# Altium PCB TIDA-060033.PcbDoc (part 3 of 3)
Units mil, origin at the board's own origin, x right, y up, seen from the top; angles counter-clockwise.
Board outline 1900 x 3360 mil, 8 copper layers (Top Layer L1, GND Plane L2, GND Plane L3, GND/Signal L4, GND Plane L5, GND Plane L6, GND Plane L7, Bottom Layer L8), stack 61.4 mil thick; 78 components, 27 nets, 146 pads, 1944 vias.
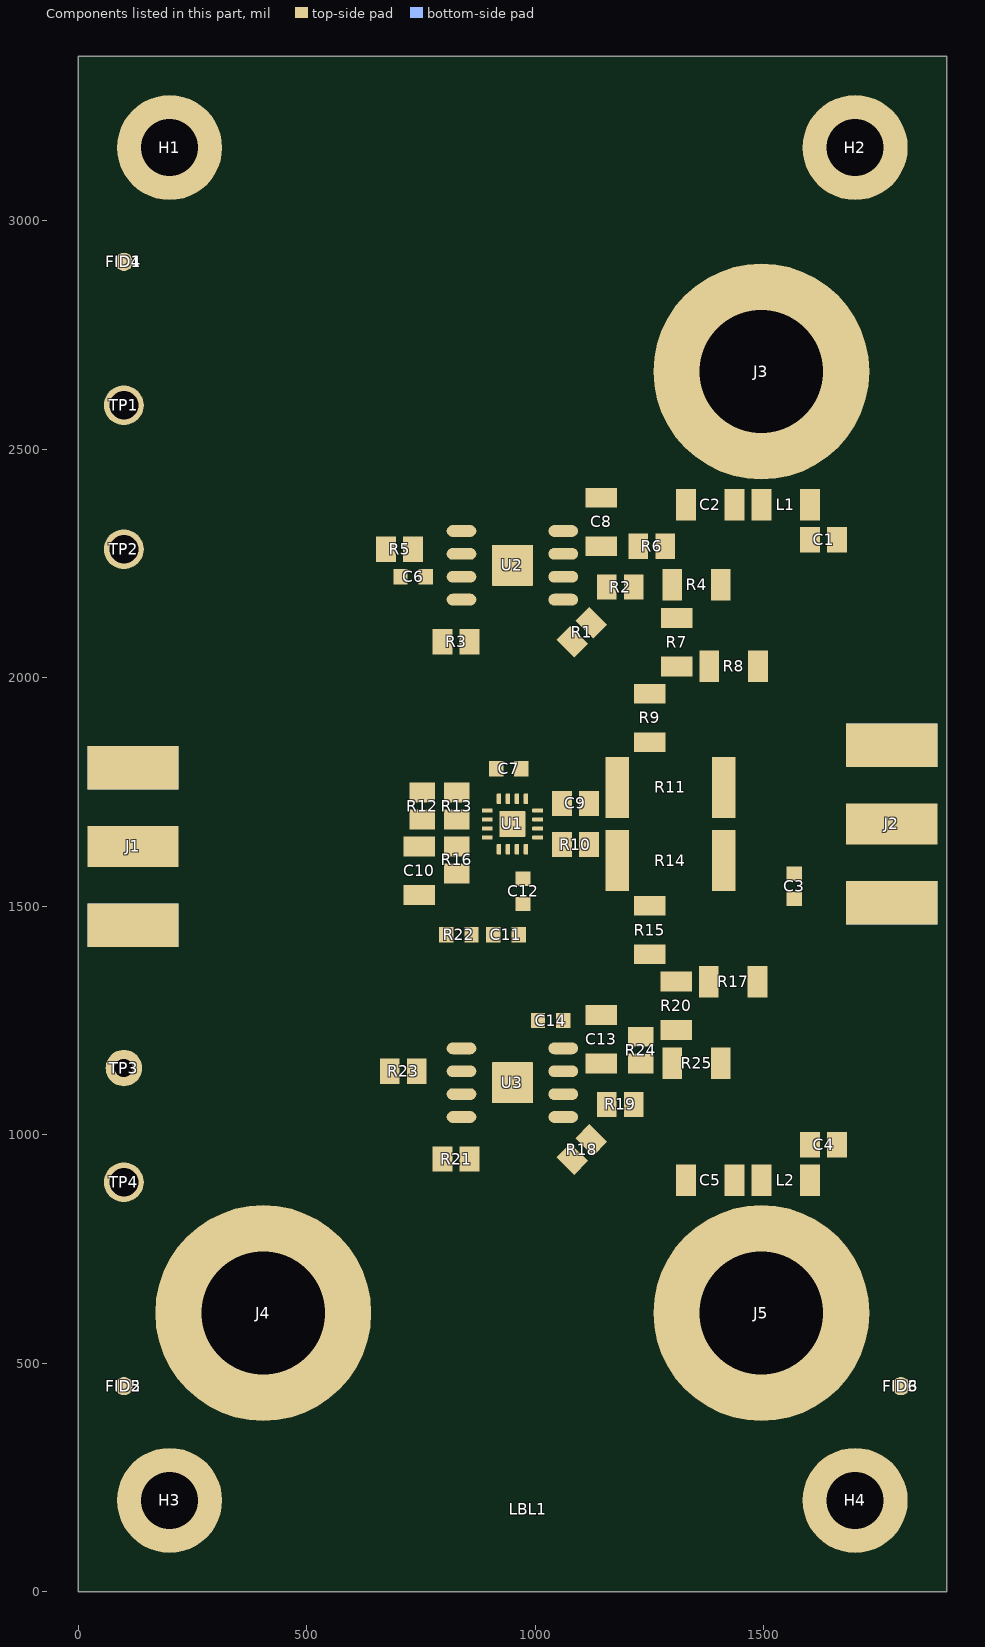
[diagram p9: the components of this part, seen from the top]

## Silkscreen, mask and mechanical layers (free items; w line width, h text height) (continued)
M9 Title Sheet:
  drawing of 57 lines, arcs and shapes, not listed
  text "1" at 739.84,8036.5 h70
  text "2" at 3235.5,8036.5 h70
  text "3" at 5724.84,8036.5 h70
  text "4" at 8231.51,8036.5 h70
  text "5" at 10730.5,8036.5 h70
  text "6" at 13235.5,8036.5 h70
  text "A" at -416.5,6893.5 h70
  text "A" at 14383.5,6893.5 h70
  text "B" at -416.5,4513.5 h70
  text "B" at 14383.5,4513.5 h70
  text "C" at -416.5,2138.5 h70
  text "C" at 14383.5,2138.5 h70
  text "PROJECT TITLE:" at 11343.5,277.5 h45
  text ".PRJ_Title" at 11393.5,144.17 h70
  text "DESIGNED FOR:" at 11343.5,-23.5 h45
  text ".PRJ_Customer" at 11393.5,-163.5 h70
  text "D" at -416.5,-231.5 h70
  text "D" at 14383.5,-231.5 h70
  text "FILE NAME:" at 11343.5,-323.5 h45
  text ".PCB_File_Name_No_Path" at 11393.5,-443.5 h70
  text "Texas Instruments (TI) and/or its licensors do not warrant the accuracy or completeness of this specification" at 6374,-605.34 h45
  text "ENGINEER:" at 11343.5,-613.5 h45
  text "LAYOUT BY:" at 12848.5,-613.5 h45
  text "or any information contained therein. TI and/or its licensors do not warrant that this design will meet" at 6329.01,-718 h45
  text ".PRJ_Engineer" at 11393.5,-768.49 h70
  text ".PCB_Layout" at 12899,-768.49 h70
  text "the specifications, will be suitable for your application or fit for any particular purpose, or will operate in" at 6329.01,-830.67 h45
  text ".Layer_Name" at 577,-858.49 h60
  text "ALTIUM DESIGNER VERSION:" at 12848.5,-923.5 h45
  text "an implementation. TI and/or its licensors do not warrant that the design is production worthy. You should" at 6329.01,-943.33 h45
  text "completely validate and test your design implementation to confirm the system functionality for your application." at 6374,-1056 h45
  text ".print_Scale" at 11393.5,-1056.83 h70
  text ".Application_BuildNumber" at 12899,-1056.83 h70
  text "1" at 739.84,-1263.5 h70
  text "2" at 3235.5,-1263.5 h70
  text "3" at 5724.84,-1263.5 h70
  text "4" at 8231.51,-1263.5 h70
  text "5" at 10730.5,-1263.5 h70
  text "6" at 13235.5,-1263.5 h70
M10 Fab Notes:
  drawing of 189 lines, arcs and shapes, not listed
  text "DESIGN INFORMATION" at 12382.02,6356.17 h60
  text "MIN. TRACK WIDTH:" at 11737.46,6224.05 h60
  text "8" at 12833.7,6224.05 h60
  text "MIL" at 12988.46,6224.05 h60
  text "MIN. CLEARANCE:" at 11737.46,6099.92 h60
  text "0.2" at 12773.7,6099.93 h60
  text "mm" at 12988.46,6099.92 h60
  text "MIN. VIA PAD SIZE:" at 11737.46,5975.8 h60
  text "24" at 12803.71,5975.8 h60
  text "MIL" at 12988.46,5975.8 h60
  text "0.05mm (2MIL)" at 12432.46,5845.9 h60
  text "MINIMUM ANNULAR RING" at 11408.23,5837.67 h60
  text "EXTERNAL" at 13140.46,5837.67 h60
  text "PER" at 11608.23,5727.55 h60
  text "IPC-D-275 CLASS 2 LEVEL C" at 11828.23,5727.54 h60
  text "MIL, HOLES" at 13316.46,5627.07 h60
  text "+/-" at 12924,5618.48 h60
  text "+/-" at 13778,5618.48 h60
  text "REGISTRATION TOLERANCES:" at 11408.23,5617.42 h60
  text "METAL" at 12608,5617.42 h60
  text "5" at 13184.2,5617.42 h60
  text "3" at 14017.2,5617.42 h60
  text "MIL" at 14133.46,5617.42 h60
  text "HOLE SIZE TOLERANCE (UNLESS OTHERWISE SPECIFIED):" at 11408.23,5519.1 h60
  text "+/-" at 13778,5516.23 h60
  text "3" at 14017.2,5515.17 h60
  text "MIL" at 14133.46,5515.17 h60
  text "MATERIAL:" at 11333.46,5377.52 h60
  text "FR-4 High Tg" at 12319.9,5249 h60
  text "X" at 12175.46,5241.01 h60
  text "FR-408" at 11754.46,5236.49 h60
  text "OTHER" at 13242.46,5236.49 h60
  text "62 MIL (1.6mm) +/-10%" at 12074.56,5093.46 h60
  text "X" at 11954.46,5091.01 h60
  text "THICKNESS:" at 11408.23,5085.24 h60
  text "OTHER" at 13359.46,5085.24 h60
  text "TOLERANCE:" at 11408.23,4946.92 h60
  text "X" at 12256.46,4946.92 h60
  text "ANSI IPC-6012 TYPE 3 CLASS 2" at 12434.48,4946.92 h60
  text "OTHER +/-" at 12434.46,4802.73 h60
  text "BOW & TWIST:" at 11408.23,4657.54 h60
  text "X" at 12256.46,4657.54 h60
  text "ANSI IPC-6012 TYPE 3 CLASS 2" at 12434.48,4657.54 h60
  text "OTHER +/-" at 12434.46,4510.85 h60
  text "DRILLING:" at 11333.46,4380.23 h60
  text "NC_DRILL FILES" at 13094.46,4275.04 h60
  text "REFERENCE:" at 11408.23,4271.1 h60
  text "X" at 12065.46,4271.01 h60
  text "AS SHOWN" at 12243.46,4271.1 h60
  text "X" at 12966.46,4271.1 h60
  text "OTHER" at 13392.46,4128.85 h60
  text "PTH COPPER THICKNESS:" at 11407.91,4125.32 h60
  text "X" at 12547.14,4125.32 h60
  text "20-30 um" at 12675.14,4125.32 h60
  text "BOARD FINISH:" at 11333.46,3977.73 h60
  text "SILKSCREEN:" at 11488.68,3867.6 h60
  text "X" at 12446.46,3867.6 h60
  text "TOP" at 12563.46,3867.6 h60
  text "X" at 12956.46,3867.6 h60
  text "BOTTOM" at 13074.46,3867.6 h60
  text "SILKSCREEN COLOR:" at 11488.68,3712.41 h60
  text "X" at 12445.46,3712.41 h60
  text "WHITE" at 12563.46,3712.41 h60
  text "OTHER" at 13074.46,3712.41 h60
  text "X" at 12576.46,3568.96 h60
  text "GREEN" at 12694.46,3568.96 h60
  text "OTHER" at 13312.46,3568.96 h60
  text "SOLDER RESIST COLOR:" at 11488.68,3562.1 h60
  text "X" at 12576.46,3414.71 h60
  text "MATTE" at 12694.46,3414.71 h60
  text "SEMI-GLOSS" at 13312,3414.07 h60
  text "IMMERSION GOLD (ENIG)" at 12394.46,3241.94 h60
  text "ENEPIG" at 13732,3234.72 h60
  text "SURFACE FINISH:" at 11333.46,3233.72 h60
  text "X" at 12216.46,3233.72 h60
  text "IMM. TIN/SILVER OR EQUIV" at 11663,3096.4 h60
  text "OTHER" at 13094.46,3092.47 h60
  text "ARRAY/PANEL:" at 11333.46,2937.09 h60
  text "CUT AND TRIM PER M1 BOARD OUTLINE" at 12394.46,2928.87 h60
  text "N.C. ROUTE" at 12394.46,2792.9 h60
  text "X" at 13082.46,2792.9 h60
  text "V. SCORE" at 13260.46,2792.9 h60
  text "CERTIFICATION:" at 11333.46,2663.77 h60
  text "MATERIALS AND WORKMANSHIP FOR ALL PCBS" at 12058.46,2663.77 h60
  text "TO MEET OR EXCEED THE REQUIREMENTS OF:" at 12058.46,2569.71 h60
  text "X" at 11695.97,2441.08 h60
  text "ANSI IPC-A-600F CLASS ->" at 11823.96,2441.08 h60
  text "X" at 13471.97,2441.08 h60
  text "2" at 13581.96,2441.08 h60
  text "1" at 13266.96,2439.58 h60
  text "3" at 13935.96,2439.58 h60
  text "X" at 12507.97,2293.39 h60
  text "RoHS" at 12635.96,2293.39 h60
  text "OTHER" at 13280.36,2293.39 h60
  text "PER ORDER" at 13677.42,2293.39 h60
  text "ALL BOARDS MUST MEET OR EXCEED UL94-V0 REQUIREMENTS." at 11361,2139.57 h60
  text "PCB MUST BEAR THE UL94V-0 UL REGISTERED MATERIAL ID NUMBER" at 11361,2023.5 h60
  text "ADDITIONAL REQUIREMENTS:" at 11333.46,1854.08 h60
  text "MICROSECTION:" at 11408.23,1746.95 h60
  text "YES" at 12313.96,1746.95 h60
  text "REQUIRED" at 13175.46,1602.62 h60
  text "BARE BOARD ELEC. TEST:" at 11408.23,1599.76 h60
  text "NONE" at 12713.96,1599.76 h60
  text "X" at 13057.46,1599.76 h60
  text "PER ORDER" at 13767.46,1599.76 h60
  text "XX MIL VIAS REQUIRE NON-CONDUCTIVE FILL AND PLANARIZE" at 11576.38,1394.82 h59
  text "XX MIL VIAS REQUIRE CONDUCTIVE FILL AND PLANARIZE" at 11584.38,1290.84 h60
  text "OUTER XX MIL TRACES REQUIRE 50 OHM SINGLE-ENDED IMPEDANCE" at 11583.39,1127.46 h58
  text "LAYER 2 & 3 (INNER LAYERS) XX MIL WIDE, XX MIL SPACE / TRACES REQUIRE 100 OHM DIFFERENTIAL IMPEDANCE" at 11575.39,891.74 h60
  text ".Layer_Name" at 577,-858.49 h60
M11 Gerber Information:
  lines w10: -292,-930.17 6308,-930.17 ; -292,-726.83 6310,-726.83 ; -292,-523.5 -292,-1133.5 3713,-1133.5 6310,-1133.5 6310,-523.5 -291.5,-523.5 -291.5,-1133.5 1284,-1133.5 ; 2173,-1133.5 2173,-523.5 ; 3440,-726.83 3440,-523.5 ; 4280,-726.83 4280,-523.5 ; 4902,-1140 4902,-937.17
  text "ALL ARTWORK VIEWED FROM TOP SIDE" at -228.5,-655.67 h60
  text "BOARD #:" at 2248,-655.67 h60
  text ".PRJ_Number" at 2793.5,-655.67 h60
  text "REV:" at 3638,-655.67 h60
  text ".PCB_Rev" at 3929.5,-655.67 h60
  text "SVN REV:" at 4476,-655.67 h60
  text ".VersionControl_RevNumber" at 4982,-655.67 h60
  text "LAYER NAME =" at -228.5,-858.49 h60
  text "TID #:" at 2248,-859 h60
  text ".TID" at 2793.5,-859 h60
  text "PLOT NAME =" at -228.5,-1064.34 h60
  text ".plot_File_Name" at 577,-1064.34 h60
  text "GENERATED    :" at 2250,-1064.34 h60
  text ".Print_Date" at 3119.5,-1064.34 h60
  text ".Print_Time" at 3848.5,-1064.34 h60
  text "TEXAS INSTRUMENTS" at 5113,-1064.34 h60
M12 Stackup:
  drawing of 503 lines, arcs and shapes, not listed
  text "Layer" at 6717.5,7807.5 h60
  text "Name" at 7127.41,7807.5 h60
  text "Material" at 8127.13,7807.5 h60
  text "Thickness" at 8986.9,7807.5 h60
  text "Constant" at 9636.74,7807.5 h60
  text "Board Layer Stack" at 10206.6,7807.5 h60
  text "1" at 6717.5,7687.5 h60
  text "Top Overlay" at 7127.41,7687.5 h60
  text "2" at 6717.5,7567.5 h60
  text "Top Solder" at 7127.41,7567.5 h60
  text "Solder Resist" at 8127.13,7567.5 h60
  text "0.40mil" at 8986.9,7567.5 h60
  text "3.5" at 9636.74,7567.5 h60
  text "3" at 6717.5,7447.5 h60
  text "Top Layer L1" at 7127.41,7447.5 h60
  text "Copper" at 8127.13,7447.5 h60
  text "2.80mil" at 8986.9,7447.5 h60
  text "4" at 6717.5,7327.5 h60
  text "Dielectric 1" at 7127.41,7327.5 h60
  text "FR-4 High Tg" at 8127.13,7327.5 h60
  text "6.00mil" at 8986.9,7327.5 h60
  text "4.6" at 9636.74,7327.5 h60
  text "5" at 6717.5,7207.5 h60
  text "GND Plane L2" at 7127.41,7207.5 h60
  text "Copper" at 8127.13,7207.5 h60
  text "2.80mil" at 8986.9,7207.5 h60
  text "6" at 6717.5,7087.5 h60
  text "Dielectric 2" at 7127.41,7087.5 h60
  text "FR-4 High Tg" at 8127.13,7087.5 h60
  text "6.00mil" at 8986.9,7087.5 h60
  text "4.6" at 9636.74,7087.5 h60
  text "7" at 6717.5,6967.5 h60
  text "GND Plane L3" at 7127.41,6967.5 h60
  text "Copper" at 8127.13,6967.5 h60
  text "2.80mil" at 8986.9,6967.5 h60
  text "8" at 6717.5,6847.5 h60
  text "Dielectric 3" at 7127.41,6847.5 h60
  text "FR-4 High Tg" at 8127.13,6847.5 h60
  text "5.00mil" at 8986.9,6847.5 h60
  text "4.6" at 9636.74,6847.5 h60
  text "9" at 6717.5,6727.5 h60
  text "GND/Signal L4" at 7127.41,6727.5 h60
  text "Copper" at 8127.13,6727.5 h60
  text "2.80mil" at 8986.9,6727.5 h60
  text "10" at 6717.5,6607.5 h60
  text "Dielectric 4" at 7127.41,6607.5 h60
  text "FR-4 High Tg" at 8127.13,6607.5 h60
  text "5.00mil" at 8986.9,6607.5 h60
  text "4.6" at 9636.74,6607.5 h60
  text "11" at 6717.5,6487.5 h60
  text "GND Plane L5" at 7127.41,6487.5 h60
  text "Copper" at 8127.13,6487.5 h60
  text "2.80mil" at 8986.9,6487.5 h60
  text "12" at 6717.5,6367.5 h60
  text "Dielectric 5" at 7127.41,6367.5 h60
  text "FR-4 High Tg" at 8127.13,6367.5 h60
  text "5.00mil" at 8986.9,6367.5 h60
  text "4.6" at 9636.74,6367.5 h60
  text "13" at 6717.5,6247.5 h60
  text "GND Plane L6" at 7127.41,6247.5 h60
  text "Copper" at 8127.13,6247.5 h60
  text "2.80mil" at 8986.9,6247.5 h60
  text "14" at 6717.5,6127.5 h60
  text "Dielectric 6" at 7127.41,6127.5 h60
  text "FR-4 High Tg" at 8127.13,6127.5 h60
  text "6.00mil" at 8986.9,6127.5 h60
  text "4.6" at 9636.74,6127.5 h60
  text "15" at 6717.5,6007.5 h60
  text "GND Plane L7" at 7127.41,6007.5 h60
  text "Copper" at 8127.13,6007.5 h60
  text "2.80mil" at 8986.9,6007.5 h60
  text "16" at 6717.5,5887.5 h60
  text "Dielectric 7" at 7127.41,5887.5 h60
  text "FR-4 High Tg" at 8127.13,5887.5 h60
  text "6.00mil" at 8986.9,5887.5 h60
  text "4.6" at 9636.74,5887.5 h60
  text "17" at 6717.5,5767.5 h60
  text "Bottom Layer L8" at 7127.41,5767.5 h60
  text "Copper" at 8127.13,5767.5 h60
  text "2.80mil" at 8986.9,5767.5 h60
  text "18" at 6717.5,5647.5 h60
  text "Bottom Solder" at 7127.41,5647.5 h60
  text "Solder Resist" at 8127.13,5647.5 h60
  text "0.40mil" at 8986.9,5647.5 h60
  text "3.5" at 9636.74,5647.5 h60
  text "19" at 6717.5,5527.5 h60
  text "Bottom Overlay" at 7127.41,5527.5 h60
  text ".Layer_Name" at 577,-858.49 h60
M13 Component Bodies Top:
  text ".Layer_Name" at 577,-858.49 h60
M14 Component Bodies Bottom:
  text ".Layer_Name" at 577,-858.49 h60
M15 Courtyards Top:
  text ".Layer_Name" at 577,-858.49 h60
M16 Courtyards Bottom:
  text ".Layer_Name" at 577,-858.49 h60
Drill Drawing:
  circle w10: c3083.72,455.32 r27.63
  lines w10: 3056.09,234.31 3111.34,234.31 3083.72,179.06 3056.09,234.31 ; 3056.09,303.38 3111.34,303.38 3111.34,358.63 3056.09,358.63 3056.09,303.38 ; 3056.09,552.02 3083.72,565.83 3111.34,552.02 3097.53,579.64 3111.34,607.27 3083.72,593.46 3056.09,607.27 3069.9,579.64 3056.09,552.02 ; 3056.09,676.34 3056.09,690.15 3069.9,703.96 3056.09,717.78 3056.09,731.59 3069.9,731.59 3083.72,717.78 3097.53,731.59 3111.34,731.59 3111.34,717.78 3097.53,703.96 3111.34,690.15 3111.34,676.34 3097.53,676.34 3083.72,690.15 3069.9,676.34 3056.09,676.34 ; 3056.09,814.47 3069.9,814.47 3083.72,800.66 3097.53,814.47 3111.34,814.47 3097.53,828.28 3111.34,842.1 3097.53,842.1 3083.72,855.91 3069.9,842.1 3056.09,842.1 3069.9,828.28 3056.09,814.47
  lines w12: 3006,141.76 6389.61,141.76 ; 3006,887.68 6389.61,887.68 ; 3343.86,17.44 3343.86,1012 ; 3675.86,17.44 3675.86,1012 ; 4312.43,17.44 4312.43,1012 ; 4571.57,17.44 4571.57,1012 ; 4946.72,17.44 4946.72,1012 ; 5823.18,17.44 5823.18,1012 ; 3006,17.44 6389.61,17.44 6389.61,1012 3006,1012 3006,17.44
  text "7.87mil (0.200mm) Holes L1 to L8 to be to be plugged with thermal/electrical conductive epoxy of manufacturers choice." at 3010,1894.03 h75
  text "Plugged vias to be plated after plugging to present flat surface to devices on L1 and L8, no potholes." at 3010,1751.48 h75
  text "7.87mil (0.200mm) Holes L5 to L8 to be to be plugged with thermal/electrical conductive epoxy of manufacturers choice." at 3010,1484.24 h75
  text "Plugged vias to be plated after plugging to present flat surface to devices on L8, no potholes." at 3010,1341.7 h75
  text "Symbol" at 3080.59,924.98 h72
  text "Quantity" at 3381.16,924.98 h72
  text "Finished Hole Size" at 3713.16,924.98 h72
  text "Plated" at 4349.72,924.98 h72
  text "Hole Type" at 4608.86,924.98 h72
  text "Drill Layer Pair" at 4984.02,924.98 h72
  text "Hole Tolerance" at 5860.48,924.98 h72
  text "978" at 3381.16,800.66 h60
  text "7.87mil (0.200mm)" at 3713.16,800.66 h60
  text "PTH" at 4349.72,800.66 h60
  text "Round" at 4608.86,800.66 h60
  text "Top Layer L1 - Bottom Layer L8" at 4984.02,800.66 h60
  text "7" at 3381.16,676.34 h60
  text "10.00mil (0.254mm)" at 3713.16,676.34 h60
  text "PTH" at 4349.72,676.34 h60
  text "Round" at 4608.86,676.34 h60
  text "Top Layer L1 - Bottom Layer L8" at 4984.02,676.34 h60
  text "1" at 3381.16,552.02 h60
  text "40.00mil (1.016mm)" at 3713.16,552.02 h60
  text "PTH" at 4349.72,552.02 h60
  text "Round" at 4608.86,552.02 h60
  text "Top Layer L1 - Bottom Layer L8" at 4984.02,552.02 h60
  text "3" at 3381.16,427.7 h60
  text "63.00mil (1.600mm)" at 3713.16,427.7 h60
  text "PTH" at 4349.72,427.7 h60
  text "Round" at 4608.86,427.7 h60
  text "Top Layer L1 - Bottom Layer L8" at 4984.02,427.7 h60
  text "4" at 3381.16,303.38 h60
  text "125.00mil (3.175mm)" at 3713.16,303.38 h60
  text "PTH" at 4349.72,303.38 h60
  text "Round" at 4608.86,303.38 h60
  text "Top Layer L1 - Bottom Layer L8" at 4984.02,303.38 h60
  text "3" at 3381.16,179.06 h60
  text "270.00mil (6.858mm)" at 3713.16,179.06 h60
  text "PTH" at 4349.72,179.06 h60
  text "Round" at 4608.86,179.06 h60
  text "Top Layer L1 - Bottom Layer L8" at 4984.02,179.06 h60
  text "996 Total" at 3381.16,54.74 h60
  text ".Layer_Name" at 577,-858.49 h60
M17 Embedded Cavity:
  text ".Layer_Name" at 577,-858.49 h60
M18 Embedded Assembly:
  text ".Layer_Name" at 577,-858.49 h60
M19 Embedded Keepout:
  text ".Layer_Name" at 577,-858.49 h60

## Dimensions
0,0 to 1900,0 on M2 Board Dimensions
0,-400 to 1000,-400 on M2 Board Dimensions
0,0 to 0,3360 on M2 Board Dimensions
